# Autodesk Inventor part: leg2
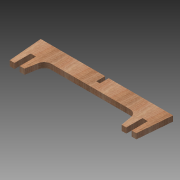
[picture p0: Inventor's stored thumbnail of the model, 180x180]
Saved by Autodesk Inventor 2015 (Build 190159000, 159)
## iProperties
Created: 2015-04
Part Number: leg2
Material: Wood (Birch)
Document SubType Name: Modeling
Designer: sungeun
Density: 0.55 g/cm^3
Appearance: Birch - Natural Polished
Author: sungeun
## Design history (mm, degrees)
sketch "Sketch1"
  geometry: L1 (-429.878, 0)-(-450, 230); L2 (-450, 230)-(0, 230); L3 (-429.878, 0)-(-329.878, 0); L4 (-329.878, 0)-(-308.718, 120); L5 (-308.718, 120)-(0, 120); L6 (0, 230)-(0, 120); L7 (450, 230)-(0, 230); L8 (429.878, 0)-(450, 230); L9 (329.878, 0)-(308.718, 120); L10 (308.718, 120)-(0, 120); L11 (429.878, 0)-(329.878, 0); 1 further point
  constraints: 22 end point, 4 symmetric about line, 3 horizontal, 1 horizontal alignment, 1 vertical, 1 vertical alignment
  dimensions: "height" = 230 distance from line of point (0, 0) L2; "d2" = 85 deg angle of L2 L1; "d3" = 100 distance of L1.start L3.end; "d4" = 120 vertical distance of L3.end L4.end; "d5" = 100 deg angle of L3 L4; "d8" = 450 distance of L1.end L2.end
extrude "Extrusion1" new body sketch "Sketch1" distance "d6" = 36 (= 3 x thickness); taper "d7" = 0 deg
sketch "Sketch2"
  geometry: L1 (-397.878, 110)-(-361.878, 110); L2 (-361.878, 110)-(-361.878, 0); L3 (-361.878, 0)-(-397.878, 0); L4 (-397.878, 0)-(-397.878, 110); L5 (-429.878, 0)-(-329.878, 0) reference; L6 (450, 230)-(-450, 230) reference; L7 (0, 230)-(0, 0); L8 (397.878, 110)-(361.878, 110); L9 (361.878, 110)-(361.878, 0); L10 (397.878, 0)-(397.878, 110); L11 (361.878, 0)-(397.878, 0); 2 further points
  constraints: 18 end point, 4 symmetric about line, 3 midpoint, 2 parallel, 1 coincident, 1 horizontal, 1 perpendicular, 1 vertical
  dimensions: "d10" = 110 distance between parallel lines of L3 L1; "d11" = 36 distance of L1.start L1.end (= 3 x thickness); "d12" = 120 distance between parallel lines of L6 L1
extrude "Extrusion2" cut sketch "Sketch2" stored distance "d13" = 10; taper "d14" = 0 deg
sketch "Sketch3"
  geometry: L1 (450, 230)-(-450, 230) reference; L2 (-12, 230)-(12, 230); L3 (12, 230)-(12, 170); L4 (12, 170)-(-12, 170); L5 (-12, 170)-(-12, 230); 2 further points
  constraints: 8 end point, 2 parallel, 1 horizontal, 1 midpoint, 1 perpendicular, 1 point on line, 1 vertical alignment
  dimensions: "d15" = 60 distance of L2.end L3.end; "d16" = 24 distance of L3.end L4.end (= 2 x thickness)
extrude "Extrusion3" cut sketch "Sketch3" stored distance "d17" = 10; taper "d18" = 0 deg
fillet "Fillet1" dims "d19" = 50
body "Solid1"
other parameters: "thickness" = 12 [user parameter; used in 3 equation terms]
